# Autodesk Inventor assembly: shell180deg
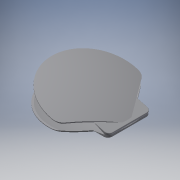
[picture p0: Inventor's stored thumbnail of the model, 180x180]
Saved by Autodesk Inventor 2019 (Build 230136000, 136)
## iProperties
Created: 2021-03
Part Number: shell180deg
Material: 一般
Document SubType Name: Assembly
Designer: kikut
Author: kikut
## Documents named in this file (2)
- F:\openFOAM\shell\shell00\cad\shell180deg.iam
- F:\openFOAM\shell\shell00\cad\shell.ipt
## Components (2 placed, 1 different names)
1. shell:1 — メイト:1, 角度:1, フラッシュ:1, メイト:2
2. shell:2 — 角度:2, フラッシュ:1, メイト:2
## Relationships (5: Mate 2, Angle 2, Flush 1)
- メイト:1 [Mate]: shell:1
- 角度:1 [Angle]: shell:1
- 角度:2 [Angle]: shell:2
- フラッシュ:1 [Flush]: shell:1 ↔ shell:2
- メイト:2 [Mate]: shell:1 ↔ shell:2
